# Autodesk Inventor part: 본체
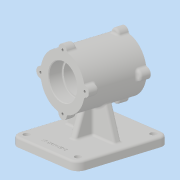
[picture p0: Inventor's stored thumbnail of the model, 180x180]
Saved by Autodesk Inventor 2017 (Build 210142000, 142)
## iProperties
Part Number: 본체
Material: 일반
Document SubType Name: Modeling
Designer: MRC
Density: 1 g/cm^3
Appearance: 기본값
Author: MRC
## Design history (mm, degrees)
sketch "스케치2"
  geometry: L1 (0, 0)-(0, 43.5); L2 (37, 0)-(37, 43.5); L3 (37, 43.5)-(23.5, 43.5); L4 (23.5, 43.5)-(23.5, 24.5); L5 (23.5, 24.5)-(21, 24.5); L6 (21, 24.5)-(21, 0); L7 (21, 0)-(37, 0); L8 (37, 0)-(37, -43.5); L9 (37, -43.5)-(23.5, -43.5); L10 (23.5, -43.5)-(23.5, -24.5); L11 (23.5, -24.5)-(21, -24.5); L12 (21, -24.5)-(21, 0); 1 further point
  constraints: 24 end point, 5 perpendicular, 4 symmetric about line, 2 vertical, 1 horizontal alignment, 1 midpoint
  dimensions: "d3" = 43.5 distance of L1.start L1.end; "d4" = 47 diameter of L4 L1; "d5" = 42 diameter of L6 L1; "d6" = 43.5 distance of L2.start L2.end; "d7" = 74 diameter of L2 L1; "d8" = 19 distance between parallel lines of L3 L5
revolve "회전1" sketch "스케치2" stored, may be unused: angle "d9" = 90 deg
sketch "스케치3"
  geometry: C1 r 7 at (0, 37); 1 further point
  constraints: 1 centre point, 1 vertical alignment
  dimensions: "d10" = 14 diameter of C1; "d11" = 37 distance of point (0, 0) C1.centre
extrude "돌출1" join sketch "스케치3" distance "d12" = 14; taper "d13" = 0 deg
sketch "스케치4"
  geometry: 2 further points
  constraints: 1 vertical alignment
  dimensions: "d14" = 37 distance of point (0, -37) point (0, 0)
hole "구멍1" sketch "스케치4" at (0, 0) diameter "d15" = 3.242; stored, may be unused: countersink angle "d19" = 90 deg, drill point angle "d21" = 118 deg; dims "d16" = 8, "d17" = 4, "d18" = 2, "d20" = 10
node "작업 평면1"
sketch "스케치5"
  geometry: L1 (43, -60)-(-43, -60); L2 (-55, -48)-(-55, 58); L3 (-43, 70)-(43, 70); L4 (55, 58)-(55, -48); A1 r 12 centre (43, -48) between (43, -60) and (55, -48); A2 r 12 centre (-43, -48) between (-55, -48) and (-43, -60); A3 r 12 centre (-43, 58) between (-43, 70) and (-55, 58); A4 r 12 centre (43, 58) between (55, 58) and (43, 70); 4 further points
  constraints: 8 end point, 8 point on circle, 8 tangent, 6 point on line, 4 centre point, 3 equal radius, 2 parallel, 1 horizontal, 1 perpendicular
  dimensions: "d26" = 130 distance of point (-55, -60) point (-55, 70); "d27" = 110 distance of point (55, -60) point (-55, -60); "d28" = 70 distance from line of L3 point (0, 0); "d29" = 55 distance from line of L4 point (0, 0); "d30" = 12 radius of A1
extrude "돌출2" join sketch "스케치5" distance "d31" = 12; taper "d32" = 0 deg
sketch "스케치7"
  geometry: L1 (-5, 5)-(5, 5); L2 (5, 5)-(5, -5); L3 (5, -5)-(-5, -5); L4 (-5, -5)-(-5, 5); 3 further points
  constraints: 8 end point, 2 midpoint, 2 parallel, 1 horizontal, 1 horizontal alignment, 1 perpendicular, 1 vertical alignment
  dimensions: "d52" = 10 distance of L1.start L1.end; "d53" = 10 distance of L1.end L2.end
extrude "돌출4" join sketch "스케치7" stored distance "d54" = 80; taper "d55" = 0 deg
sketch "스케치8"
  geometry: L1 (-41, -70)-(-25.336, -26.964); L2 (25.336, -26.964)-(41, -70); L3 (43, -70)-(-43, -70) reference; L4 (-55, -82)-(-55, -70) reference; L5 (55, -82)-(55, -70) reference; A1 r 37 centre (0, 0) between (-36.338, -6.969) and (-6.969, -36.338) reference; A2 r 37 centre (0, 0) between (6.969, -36.338) and (36.338, -6.969) reference; 1 further point
  constraints: 4 end point, 2 point on circle, 2 point on line
  dimensions: "d56" = 14 distance from line of L1.start L4; "d57" = 14 distance from line of L5 L2.end; "d58" = 110 deg dimension on L1.start L4.end L1.end; "d59" = 110 deg dimension on L2.end L5.end L2.start
feature "리브1" dims "d60" = 1, "d61" = 10, "d62" = 0, "d63" = 0, "d64" = 1, "d65" = 1
feature "리브2" dims "d66" = 1, "d67" = 10, "d68" = 0, "d69" = 0, "d70" = 1, "d71" = 1
sketch "스케치9"
  geometry: L1 (-70, 30)-(-37, 17.989); L2 (-37, -17.989)-(-70, -30); L3 (-37, 29.5)-(-37, -29.5) reference; L4 (-70, -48)-(-70, 58) reference; 1 further point
  constraints: 4 end point, 4 point on line
  dimensions: "d72" = 60 distance of L2.end L1.start; "d73" = 30 vertical distance of L1.start point (0, 0); "d74" = 110 deg dimension on L1.start L1.end L4.end; "d75" = 110 deg dimension on L2.end L4.start L2.start
feature "리브3" dims "d76" = 1, "d77" = 10, "d78" = 0, "d79" = 0, "d80" = 1, "d81" = 1
feature "리브4" dims "d82" = 1, "d83" = 10, "d84" = 0, "d85" = 0, "d86" = 1, "d87" = 1
fillet "모깎기1" dims "d88" = 1
chamfer "모따기1" distance "d89" = 1; stored, may be unused: second distance "d90" = 2, angle "d91" = 45 deg
fillet "모깎기2" dims "d92" = 3
fillet "모깎기3" dims "d93" = 3
sketch "스케치10"
  geometry: L1 (43, 60)-(-43, 60) reference; L2 (-55, 48)-(-55, -58) reference; C1 r 4.5 at (-43, 48); 1 further point
  constraints: 1 centre point
  dimensions: "d94" = 9 diameter of C1; "d96" = 12 distance from line of L2 C1.centre; "d97" = 12 distance from line of L1 C1.centre
extrude "돌출5" cut sketch "스케치10" stored distance "d98" = 80; taper "d99" = 0 deg
sketch "스케치11"
  geometry: 2 further points
  constraints: 1 vertical alignment, 1 other
  dimensions: "d106" = 55 distance of point (0, 0) point (0, -55)
feature "엠보싱1" sketch "스케치11" dims "d3" = 43.5, "d4" = 47, "d5" = 42, "d6" = 43.5, "d7" = 74, "d8" = 19, "d107" = 0.5, "d108" = 0
node "솔리드1"
pattern_circular "원형 패턴1" dims angle "d23" = 360 deg
mirror "미러1"
pattern_linear "직사각형 패턴1" dims "d102" = 86, "d105" = 106
other parameters: "d25" = -82
